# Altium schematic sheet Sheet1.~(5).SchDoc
size A3; SheetNumber: 1; SheetTotal: 1
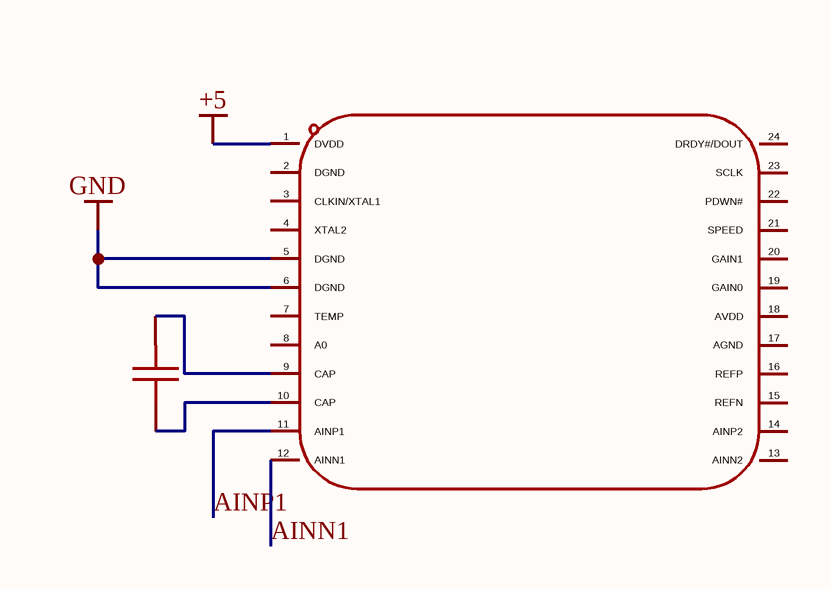
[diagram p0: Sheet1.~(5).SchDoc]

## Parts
C??  cga0603x7r104k500jt  [C0603]  (value not drawn)
U??  ads1232ipwr  [TSSOP-24_L7.8-W4.4-P0.65-LS6.4-BL]  (value not drawn)

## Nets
+5: U??.1(DVDD)
GND: U??.5(DGND) U??.6(DGND)
AINN1: U??.12(AINN1)
AINP1: U??.11(AINP1)
NetC??_1: C??.1 U??.10(CAP)
NetC??_2: C??.2 U??.9(CAP)

Not connected (* = marked no-connect by the designer): U?? 2(DGND) 3(CLKIN/XTAL1) 4(XTAL2) 7(TEMP) 8(A0) 13(AINN2) 14(AINP2) 15(REFN) 16(REFP) 17(AGND) 18(AVDD) 19(GAIN0) 20(GAIN1) 21(SPEED) 22(PDWN#) 23(SCLK) 24(DRDY#/DOUT)

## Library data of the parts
C?? = cga0603x7r104k500jt: 容值:100nF;精度:±10%;额定电压:50V;温度系数:X7R;; Manufacturer: HRE(芯声); AddInBom: yes; ModelId: ac125912035d415993ca9572d50418b1; ModelName: C0603_L1.6-W0.8-H0.8; ModelTransform: 62.992,31.496,0,0,0,0,0,0,0; Value: 100nF; Tolerance: ±10%; Voltage Rating: 50V; Temperature Coefficient: X7R
U?? = ads1232ipwr: 分辨率(位):24;采样率:10Hz;工作电压:2.7V~5.3V;接口类型:SPI;; Manufacturer: TI(德州仪器); AddInBom: yes; ModelId: 57e278220af748a2882c4abba4094eb9; ModelName: TSSOP-24_L7.8-W4.4-H1.0-LS6.4-P0.65; ModelTransform: 252.188,307.086,0,90,0,0,0,0,0; Resolution (Bits): 24; Sampling Rate: 10Hz; number of channels: 2; Interface: SPI; differential input: 是; Clock/Oscillator: 内置；外置; Clock Frequency: 4.9152MHz；200kHz~8MHz; Voltage Reference: 外置; Programmable Gain: 支持; Temperature Sensors: 内置; ADC architecture: Sigma-Delta; Data rate: 80Hz；10Hz; Quiescent Current (Iq): 1.3uA; Full-Scale Range(FSR): 39mV；1.25V；19.5mV；2.5V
